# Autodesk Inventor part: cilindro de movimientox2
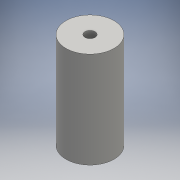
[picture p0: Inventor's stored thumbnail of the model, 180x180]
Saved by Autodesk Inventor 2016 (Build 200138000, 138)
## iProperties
Created: 2016-06
Part Number: cilindro de movimientox2
Material: Genérico
Document SubType Name: Modeling
Designer: adm
Density: 1 g/cm^3
Appearance: Valor por defecto
Author: adm
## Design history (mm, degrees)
sketch "Boceto1"
  geometry: C1 r 25 at (0, 0); 1 further point
  constraints: 1 centre point, 1 coincident
  dimensions: "d0" = 50 diameter of C1
extrude "Extrusión1" new body sketch "Boceto1" distance "d1" = 100; taper "d2" = 0 deg
sketch "Boceto2"
  geometry: C1 r 5.25 at (0, 0); 1 further point
  constraints: 1 centre point, 1 coincident
  dimensions: "d3" = 10.5 diameter of C1
extrude "Extrusión2" cut sketch "Boceto2" distance "d4" = 100; taper "d5" = 0 deg
node "Sólido1"
